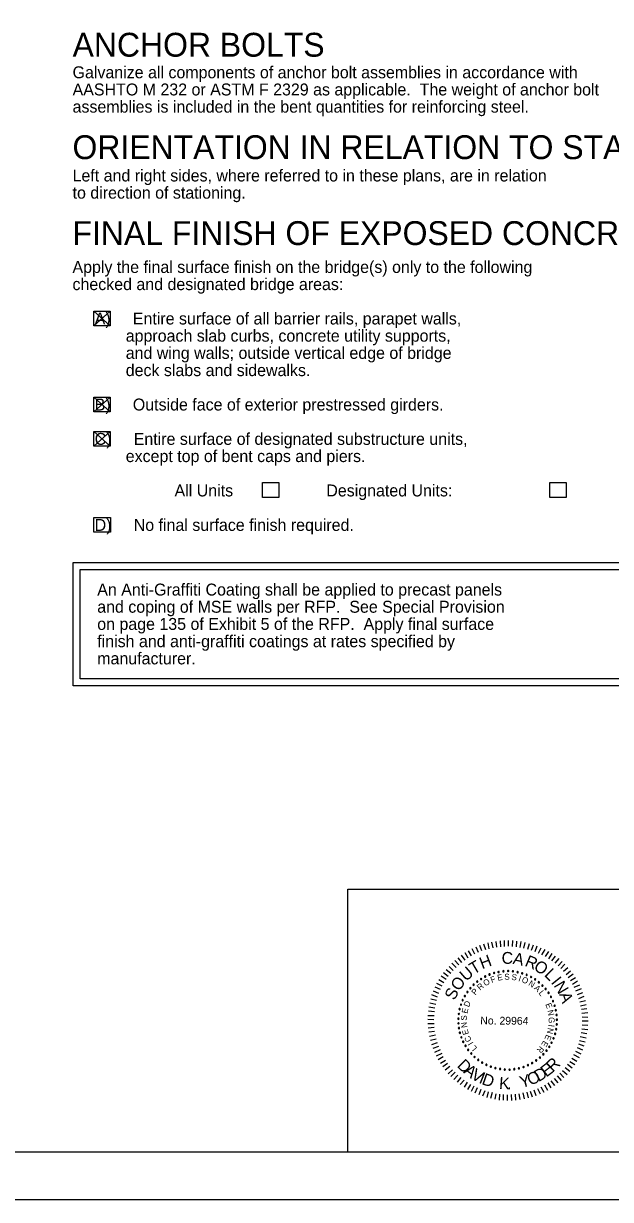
# Model space of a CAD drawing. Extents: x -1.3 to 34.8, y 0.8 to 22.8.
# Drawn here: x 17.92 to 24.06, y 0.82 to 13.14 of the extents above; entities that cross this region are included whole.
import ezdxf

# ---------------------------------------------------------------- set-up
doc = ezdxf.new("R2010")
doc.units = 0
for name, color, linetype in [('BR_BORDER LINES', 7, 'Continuous'), ('BR_TEXT', 7, 'Continuous'), ('Level 31', 7, 'Continuous')]:
    doc.layers.add(name, color=color, linetype=linetype)

msp = doc.modelspace()

# ---------------------------------------------------------------- linework, layer by layer
at = {"layer": 'BR_BORDER LINES'}
for p, q in [((21.311, 4.068), (26.676, 4.068)), ((21.311, 1.318), (21.311, 4.068)), ((0.511, 1.318), (34.177, 1.318))]:
    msp.add_line(p, q, dxfattribs=at)
at = {"layer": 'BR_TEXT'}
for p, q in [((18.654, 10.123), (18.825, 9.968)), ((18.825, 10.123), (18.654, 9.968)), ((18.826, 9.223), (18.655, 9.068)), ((18.655, 9.223), (18.826, 9.068)), ((18.826, 8.862), (18.655, 8.708)), ((18.655, 8.862), (18.826, 8.708)), ((22.678, 3.405), (22.654, 3.461)), ((22.716, 3.421), (22.695, 3.48)), ((22.756, 3.434), (22.734, 3.492)), ((22.792, 3.444), (22.779, 3.505)), ((22.833, 3.454), (22.819, 3.513)), ((22.873, 3.461), (22.864, 3.522)), ((22.912, 3.465), (22.909, 3.526)), ((22.952, 3.468), (22.952, 3.532)), ((22.994, 3.47), (22.994, 3.532)), ((23.036, 3.467), (23.038, 3.531)), ((23.076, 3.464), (23.081, 3.525)), ((23.115, 3.459), (23.126, 3.52)), ((23.155, 3.451), (23.169, 3.51)), ((23.196, 3.441), (23.212, 3.501)), ((23.233, 3.43), (23.255, 3.487)), ((23.272, 3.417), (23.294, 3.475)), ((23.308, 3.399), (23.336, 3.455)), ((22.506, 3.3), (22.466, 3.35)), ((22.54, 3.325), (22.501, 3.376)), ((22.571, 3.346), (22.54, 3.401)), ((22.606, 3.37), (22.576, 3.424)), ((22.641, 3.388), (22.614, 3.444)), ((23.344, 3.382), (23.376, 3.437)), ((23.382, 3.364), (23.414, 3.417)), ((23.415, 3.339), (23.449, 3.393)), ((23.448, 3.318), (23.485, 3.368)), ((23.481, 3.292), (23.522, 3.341)), ((22.389, 3.186), (22.34, 3.225)), ((22.414, 3.217), (22.371, 3.26)), ((22.444, 3.248), (22.399, 3.292)), ((22.473, 3.275), (22.431, 3.32)), ((23.512, 3.266), (23.556, 3.311)), ((23.54, 3.239), (23.584, 3.282)), ((23.569, 3.208), (23.616, 3.249)), ((23.596, 3.176), (23.642, 3.214)), ((22.3, 3.052), (22.243, 3.08)), ((22.317, 3.087), (22.263, 3.119)), ((22.341, 3.123), (22.288, 3.156)), ((22.363, 3.152), (22.314, 3.192)), ((23.619, 3.142), (23.669, 3.181)), ((23.641, 3.113), (23.694, 3.145)), ((23.664, 3.075), (23.717, 3.107)), ((22.252, 2.937), (22.191, 2.96)), ((22.265, 2.977), (22.207, 2.999)), ((22.282, 3.016), (22.225, 3.041)), ((23.681, 3.041), (23.739, 3.068)), ((23.699, 3.004), (23.756, 3.028)), ((23.716, 2.965), (23.773, 2.986)), ((22.233, 2.859), (22.17, 2.875)), ((22.24, 2.901), (22.179, 2.916)), ((23.729, 2.925), (23.787, 2.947)), ((23.739, 2.889), (23.799, 2.903)), ((23.747, 2.846), (23.808, 2.861)), ((22.215, 2.742), (22.15, 2.743)), ((22.218, 2.782), (22.156, 2.789)), ((22.222, 2.823), (22.161, 2.831)), ((23.756, 2.81), (23.815, 2.818)), ((23.762, 2.769), (23.823, 2.775)), ((23.764, 2.73), (23.824, 2.729)), ((22.213, 2.701), (22.15, 2.702)), ((22.214, 2.658), (22.15, 2.657)), ((22.216, 2.62), (22.154, 2.613)), ((23.761, 2.607), (23.822, 2.599)), ((23.763, 2.646), (23.823, 2.643)), ((23.766, 2.688), (23.827, 2.688)), ((22.22, 2.579), (22.159, 2.57)), ((22.23, 2.539), (22.167, 2.526)), ((22.237, 2.497), (22.176, 2.483)), ((23.736, 2.484), (23.796, 2.469)), ((23.745, 2.526), (23.805, 2.512)), ((23.754, 2.566), (23.813, 2.556)), ((22.248, 2.46), (22.186, 2.439)), ((22.26, 2.421), (22.202, 2.4)), ((22.277, 2.384), (22.219, 2.357)), ((22.294, 2.348), (22.237, 2.318)), ((23.694, 2.372), (23.75, 2.344)), ((23.711, 2.409), (23.768, 2.387)), ((23.725, 2.448), (23.783, 2.426)), ((22.311, 2.311), (22.256, 2.28)), ((22.334, 2.274), (22.28, 2.242)), ((22.356, 2.244), (22.306, 2.208)), ((23.612, 2.234), (23.661, 2.197)), ((23.634, 2.263), (23.687, 2.231)), ((23.657, 2.3), (23.71, 2.268)), ((23.675, 2.336), (23.733, 2.306)), ((22.381, 2.211), (22.331, 2.172)), ((22.406, 2.177), (22.362, 2.136)), ((22.435, 2.151), (22.39, 2.106)), ((22.464, 2.121), (22.421, 2.075)), ((22.496, 2.095), (22.455, 2.048)), ((23.503, 2.112), (23.545, 2.066)), ((23.531, 2.142), (23.574, 2.096)), ((23.56, 2.168), (23.607, 2.126)), ((23.588, 2.201), (23.634, 2.161)), ((22.529, 2.069), (22.489, 2.021)), ((22.56, 2.047), (22.529, 1.995)), ((22.595, 2.024), (22.564, 1.971)), ((22.629, 2.004), (22.602, 1.949)), ((22.666, 1.987), (22.641, 1.931)), ((23.297, 1.982), (23.324, 1.926)), ((23.333, 1.999), (23.363, 1.943)), ((23.371, 2.018), (23.402, 1.964)), ((23.404, 2.04), (23.437, 1.987)), ((23.438, 2.061), (23.474, 2.013)), ((23.471, 2.087), (23.511, 2.039)), ((22.704, 1.969), (22.682, 1.913)), ((22.744, 1.957), (22.721, 1.899)), ((22.78, 1.945), (22.765, 1.886)), ((22.821, 1.938), (22.806, 1.876)), ((22.86, 1.926), (22.85, 1.868)), ((22.9, 1.922), (22.895, 1.86)), ((22.939, 1.919), (22.939, 1.857)), ((22.981, 1.916), (22.981, 1.855)), ((23.023, 1.918), (23.024, 1.856)), ((23.064, 1.92), (23.067, 1.858)), ((23.102, 1.924), (23.112, 1.866)), ((23.143, 1.935), (23.156, 1.873)), ((23.184, 1.941), (23.199, 1.882)), ((23.221, 1.953), (23.242, 1.895)), ((23.26, 1.965), (23.281, 1.908))]:
    msp.add_line(p, q, dxfattribs=at)
for points in [[(18.654, 10.123), (18.825, 10.123), (18.825, 9.968), (18.654, 9.968)], [(18.654, 10.123), (18.825, 10.123), (18.825, 9.968), (18.654, 9.968)], [(18.655, 9.223), (18.826, 9.223), (18.826, 9.068), (18.655, 9.068)], [(18.655, 8.862), (18.826, 8.862), (18.826, 8.708), (18.655, 8.708)], [(20.419, 8.327), (20.59, 8.327), (20.59, 8.172), (20.419, 8.172)], [(23.427, 8.327), (23.598, 8.327), (23.598, 8.172), (23.427, 8.172)], [(18.655, 7.961), (18.827, 7.961), (18.827, 7.806), (18.655, 7.806)], [(18.438, 7.489), (24.798, 7.489), (24.798, 6.198), (18.438, 6.198)], [(18.512, 7.415), (24.724, 7.415), (24.724, 6.272), (18.512, 6.272)]]:
    msp.add_lwpolyline(points, close=True, dxfattribs=at)
for centre, start, end in [((22.89, 3.201), 10.6038, 190.6038), ((22.89, 3.201), 190.6038, 10.6038), ((22.94, 3.208), 5.0653, 185.0653), ((22.94, 3.208), 185.0653, 5.0653), ((22.99, 3.21), 359.5268, 179.5268), ((22.99, 3.21), 179.5268, 359.5268), ((23.039, 3.207), 353.9884, 173.9884), ((23.039, 3.207), 173.9884, 353.9884), ((23.089, 3.199), 348.4499, 168.4499), ((22.666, 3.1), 38.2961, 218.2961), ((22.666, 3.1), 218.2961, 38.2961), ((22.706, 3.128), 32.7576, 212.7576), ((22.706, 3.128), 212.7576, 32.7576), ((22.749, 3.153), 27.2191, 207.2191), ((22.749, 3.153), 207.2191, 27.2191), ((22.795, 3.174), 21.6807, 201.6807), ((22.795, 3.174), 201.6807, 21.6807), ((22.842, 3.19), 16.1422, 196.1422), ((22.842, 3.19), 196.1422, 16.1422), ((23.089, 3.199), 168.4499, 348.4499), ((23.137, 3.187), 342.9114, 162.9114), ((23.137, 3.187), 162.9114, 342.9114), ((23.184, 3.17), 337.373, 157.373), ((23.184, 3.17), 157.373, 337.373), ((23.229, 3.148), 151.8345, 331.8345), ((23.229, 3.148), 331.8345, 151.8345), ((23.271, 3.123), 146.2961, 326.2961), ((23.271, 3.123), 326.2961, 146.2961), ((23.311, 3.093), 140.7576, 320.7576), ((23.311, 3.093), 320.7576, 140.7576), ((22.536, 2.949), 60.4499, 240.4499), ((22.563, 2.991), 54.9114, 234.9114), ((22.563, 2.991), 234.9114, 54.9114), ((22.594, 3.031), 49.373, 229.373), ((22.594, 3.031), 229.373, 49.373), ((22.628, 3.067), 43.8345, 223.8345), ((22.628, 3.067), 223.8345, 43.8345), ((23.348, 3.059), 135.2191, 315.2191), ((23.348, 3.059), 315.2191, 135.2191), ((23.382, 3.023), 129.6807, 309.6807), ((23.382, 3.023), 309.6807, 129.6807), ((23.412, 2.983), 124.1422, 304.1422), ((23.412, 2.983), 304.1422, 124.1422), ((22.496, 2.859), 71.5268, 251.5268), ((22.496, 2.859), 251.5268, 71.5268), ((22.514, 2.905), 65.9884, 245.9884), ((22.514, 2.905), 245.9884, 65.9884), ((22.536, 2.949), 240.4499, 60.4499), ((23.438, 2.94), 118.6038, 298.6038), ((23.438, 2.94), 298.6038, 118.6038), ((23.459, 2.895), 113.0653, 293.0653), ((23.459, 2.895), 293.0653, 113.0653), ((23.476, 2.848), 107.5268, 287.5268), ((23.476, 2.848), 287.5268, 107.5268), ((22.469, 2.712), 88.1422, 268.1422), ((22.473, 2.762), 82.6038, 262.6038), ((22.469, 2.712), 268.1422, 88.1422), ((22.473, 2.762), 262.6038, 82.6038), ((22.482, 2.811), 77.0653, 257.0653), ((22.482, 2.811), 257.0653, 77.0653), ((23.489, 2.8), 101.9884, 281.9884), ((23.489, 2.8), 281.9884, 101.9884), ((23.497, 2.751), 96.4499, 276.4499), ((23.497, 2.751), 276.4499, 96.4499), ((22.47, 2.662), 93.6807, 273.6807), ((22.475, 2.613), 99.2191, 279.2191), ((22.47, 2.662), 273.6807, 93.6807), ((22.475, 2.613), 279.2191, 99.2191), ((23.492, 2.602), 79.8345, 259.8345), ((23.498, 2.652), 85.373, 265.373), ((23.492, 2.602), 259.8345, 79.8345), ((23.5, 2.701), 90.9114, 270.9114), ((23.498, 2.652), 265.373, 85.373), ((23.5, 2.701), 270.9114, 90.9114), ((22.485, 2.564), 104.7576, 284.7576), ((22.485, 2.564), 284.7576, 104.7576), ((22.5, 2.516), 110.2961, 290.2961), ((22.5, 2.516), 290.2961, 110.2961), ((22.52, 2.47), 115.8345, 295.8345), ((22.52, 2.47), 295.8345, 115.8345), ((23.444, 2.461), 63.2191, 243.2191), ((23.444, 2.461), 243.2191, 63.2191), ((23.465, 2.506), 68.7576, 248.7576), ((23.465, 2.506), 248.7576, 68.7576), ((23.481, 2.554), 74.2961, 254.2961), ((23.481, 2.554), 254.2961, 74.2961), ((22.544, 2.427), 121.373, 301.373), ((22.544, 2.427), 301.373, 121.373), ((22.571, 2.385), 126.9114, 306.9114), ((22.571, 2.385), 306.9114, 126.9114), ((22.603, 2.347), 132.4499, 312.4499), ((22.603, 2.347), 312.4499, 132.4499), ((23.358, 2.339), 46.6038, 226.6038), ((23.358, 2.339), 226.6038, 46.6038), ((23.391, 2.377), 52.1422, 232.1422), ((23.391, 2.377), 232.1422, 52.1422), ((23.42, 2.418), 57.6807, 237.6807), ((23.42, 2.418), 237.6807, 57.6807), ((22.638, 2.312), 137.9884, 317.9884), ((22.638, 2.312), 317.9884, 137.9884), ((22.677, 2.28), 143.5268, 323.5268), ((22.677, 2.28), 323.5268, 143.5268), ((22.718, 2.252), 149.0653, 329.0653), ((22.718, 2.252), 329.0653, 149.0653), ((22.762, 2.229), 154.6038, 334.6038), ((22.762, 2.229), 334.6038, 154.6038), ((23.197, 2.224), 24.4499, 204.4499), ((23.197, 2.224), 204.4499, 24.4499), ((23.241, 2.247), 29.9884, 209.9884), ((23.241, 2.247), 209.9884, 29.9884), ((23.283, 2.274), 35.5268, 215.5268), ((23.283, 2.274), 215.5268, 35.5268), ((23.322, 2.305), 41.0653, 221.0653), ((23.322, 2.305), 221.0653, 41.0653), ((22.808, 2.209), 160.1422, 340.1422), ((22.808, 2.209), 340.1422, 160.1422), ((22.856, 2.195), 345.6807, 165.6807), ((22.856, 2.195), 165.6807, 345.6807), ((22.905, 2.185), 351.2191, 171.2191), ((22.905, 2.185), 171.2191, 351.2191), ((22.954, 2.179), 356.7576, 176.7576), ((22.954, 2.179), 176.7576, 356.7576), ((23.004, 2.179), 2.2961, 182.2961), ((23.004, 2.179), 182.2961, 2.2961), ((23.054, 2.183), 7.8345, 187.8345), ((23.054, 2.183), 187.8345, 7.8345), ((23.103, 2.192), 13.373, 193.373), ((23.103, 2.192), 193.373, 13.373), ((23.151, 2.206), 18.9114, 198.9114), ((23.151, 2.206), 198.9114, 18.9114)]:
    msp.add_arc(centre, 0.00701, start, end, dxfattribs=at)
at = {"layer": 'Level 31'}
msp.add_lwpolyline([(-1.323, 0.818), (34.677, 0.818), (34.677, 22.818), (-1.323, 22.818)], close=True, dxfattribs=at)

# ---------------------------------------------------------------- texts
at = {"layer": 'BR_TEXT'}
for s, height, p in [('ANCHOR BOLTS', 0.25, (18.431, 12.788)), ('Galvanize all components of anchor bolt assemblies in accordance with ', 0.125, (18.431, 12.562)), ('AASHTO M 232 or ASTM F 2329 as applicable.  The weight of anchor bolt ', 0.125, (18.431, 12.382)), ('assemblies is included in the bent quantities for reinforcing steel.  ', 0.125, (18.431, 12.202)), ('ORIENTATION IN RELATION TO STATIONING', 0.25, (18.43, 11.715)), ('Left and right sides, where referred to in these plans, are in relation ', 0.125, (18.431, 11.481)), ('to direction of stationing.', 0.125, (18.431, 11.301)), ('FINAL FINISH OF EXPOSED CONCRETE SURFACES', 0.25, (18.43, 10.815)), ('Apply the final surface finish on the bridge(s) only to the following ', 0.125, (18.43, 10.523)), ('checked and designated bridge areas:', 0.125, (18.43, 10.343)), ('     A)     Entire surface of all barrier rails, parapet walls, ', 0.125, (18.43, 9.983)), ('            approach slab curbs, concrete utility supports,', 0.125, (18.43, 9.803)), ('            and wing walls; outside vertical edge of bridge', 0.125, (18.43, 9.623)), ('            deck slabs and sidewalks.', 0.125, (18.43, 9.442)), ('     B)     Outside face of exterior prestressed girders.', 0.125, (18.43, 9.082)), ('     C)     Entire surface of designated substructure units,', 0.125, (18.43, 8.722)), ('            except top of bent caps and piers.', 0.125, (18.43, 8.542)), ('                       All Units                     Designated Units:', 0.125, (18.43, 8.182)), ('     D)     No final surface finish required.  ', 0.125, (18.43, 7.821)), ('An Anti-Graffiti Coating shall be applied to precast panels ', 0.125, (18.689, 7.144)), ('and coping of MSE walls per RFP.  See Special Provision', 0.125, (18.689, 6.964)), ('on page 135 of Exhibit 5 of the RFP.  Apply final surface', 0.125, (18.689, 6.784)), ('finish and anti-graffiti coatings at rates specified by ', 0.125, (18.689, 6.603)), ('manufacturer.', 0.125, (18.689, 6.423))]:
    msp.add_text(s, height=height, dxfattribs=at).set_placement(p)
for s, height, rotation, p in [('T', 0.124, 30.4992, (22.629, 3.172)), ('H', 0.124, 20.3637, (22.717, 3.229)), ('C', 0.124, 359.5482, (22.921, 3.287)), ('A', 0.124, 348.1981, (23.033, 3.288)), ('R', 0.124, 337.4344, (23.156, 3.268)), ('U', 0.124, 40.8022, (22.548, 3.097)), ('O', 0.124, 326.5869, (23.248, 3.232)), ('L', 0.124, 315.9488, (23.361, 3.164)), ('O', 0.124, 52.0267, (22.473, 2.993)), ('R', 0.0622, 40.3949, (22.695, 3.006)), ('O', 0.0622, 30.8477, (22.751, 3.05)), ('F', 0.0622, 20.6127, (22.818, 3.086)), ('E', 0.0622, 11.4103, (22.883, 3.108)), ('S', 0.0622, 2.208, (22.951, 3.119)), ('S', 0.0622, 352.6608, (23.022, 3.119)), ('I', 0.0622, 343.1136, (23.093, 3.107)), ('O', 0.0622, 338.4392, (23.126, 3.097)), ('N', 0.0622, 328.2042, (23.196, 3.065)), ('I', 0.124, 308.6613, (23.432, 3.09)), ('N', 0.124, 300.7037, (23.463, 3.06)), ('S', 0.124, 63.2511, (22.428, 2.897)), ('P', 0.0622, 49.9421, (22.646, 2.954)), ('A', 0.0622, 318.657, (23.255, 3.025)), ('L', 0.0622, 309.4546, (23.304, 2.978)), ('A', 0.124, 289.4792, (23.522, 2.967)), ('D', 0.0622, 69.0364, (22.579, 2.828)), ('E', 0.0622, 291.049, (23.378, 2.862)), ('S', 0.0622, 87.786, (22.557, 2.691)), ('E', 0.0622, 78.2388, (22.563, 2.762)), ('No. 29964', 0.0817, 359.5268, (22.698, 2.652)), ('N', 0.0622, 281.8466, (23.4, 2.797)), ('G', 0.0622, 272.2995, (23.412, 2.727)), ('N', 0.0622, 97.3332, (22.563, 2.62)), ('E', 0.0622, 106.5355, (22.58, 2.553)), ('N', 0.0622, 257.7339, (23.407, 2.619)), ('I', 0.0622, 262.4084, (23.412, 2.653)), ('C', 0.0622, 116.4266, (22.61, 2.486)), ('I', 0.0622, 121.1011, (22.628, 2.456)), ('E', 0.0622, 238.9844, (23.361, 2.487)), ('E', 0.0622, 248.1867, (23.389, 2.55)), ('L', 0.0622, 129.9595, (22.669, 2.404)), ('R', 0.0622, 229.782, (23.324, 2.43)), ('D', 0.124, 315.4053, (22.448, 2.213)), ('A', 0.124, 322.8377, (22.515, 2.147)), ('E', 0.124, 37.5339, (23.389, 2.094)), ('R', 0.124, 44.5947, (23.459, 2.147)), ('V', 0.124, 330.5179, (22.592, 2.089)), ('I', 0.124, 338.1981, (22.676, 2.042)), ('D', 0.124, 340.7995, (22.706, 2.028)), ('K', 0.124, 356.098, (22.892, 1.978)), ('Y', 0.124, 14.8649, (23.127, 1.985)), ('O', 0.124, 22.4212, (23.219, 2.01)), ('D', 0.124, 30.1015, (23.308, 2.047)), ('.', 0.124, 3.1588, (22.98, 1.971))]:
    msp.add_text(s, height=height, rotation=rotation, dxfattribs=at).set_placement(p)

doc.saveas('drawing.dxf')
